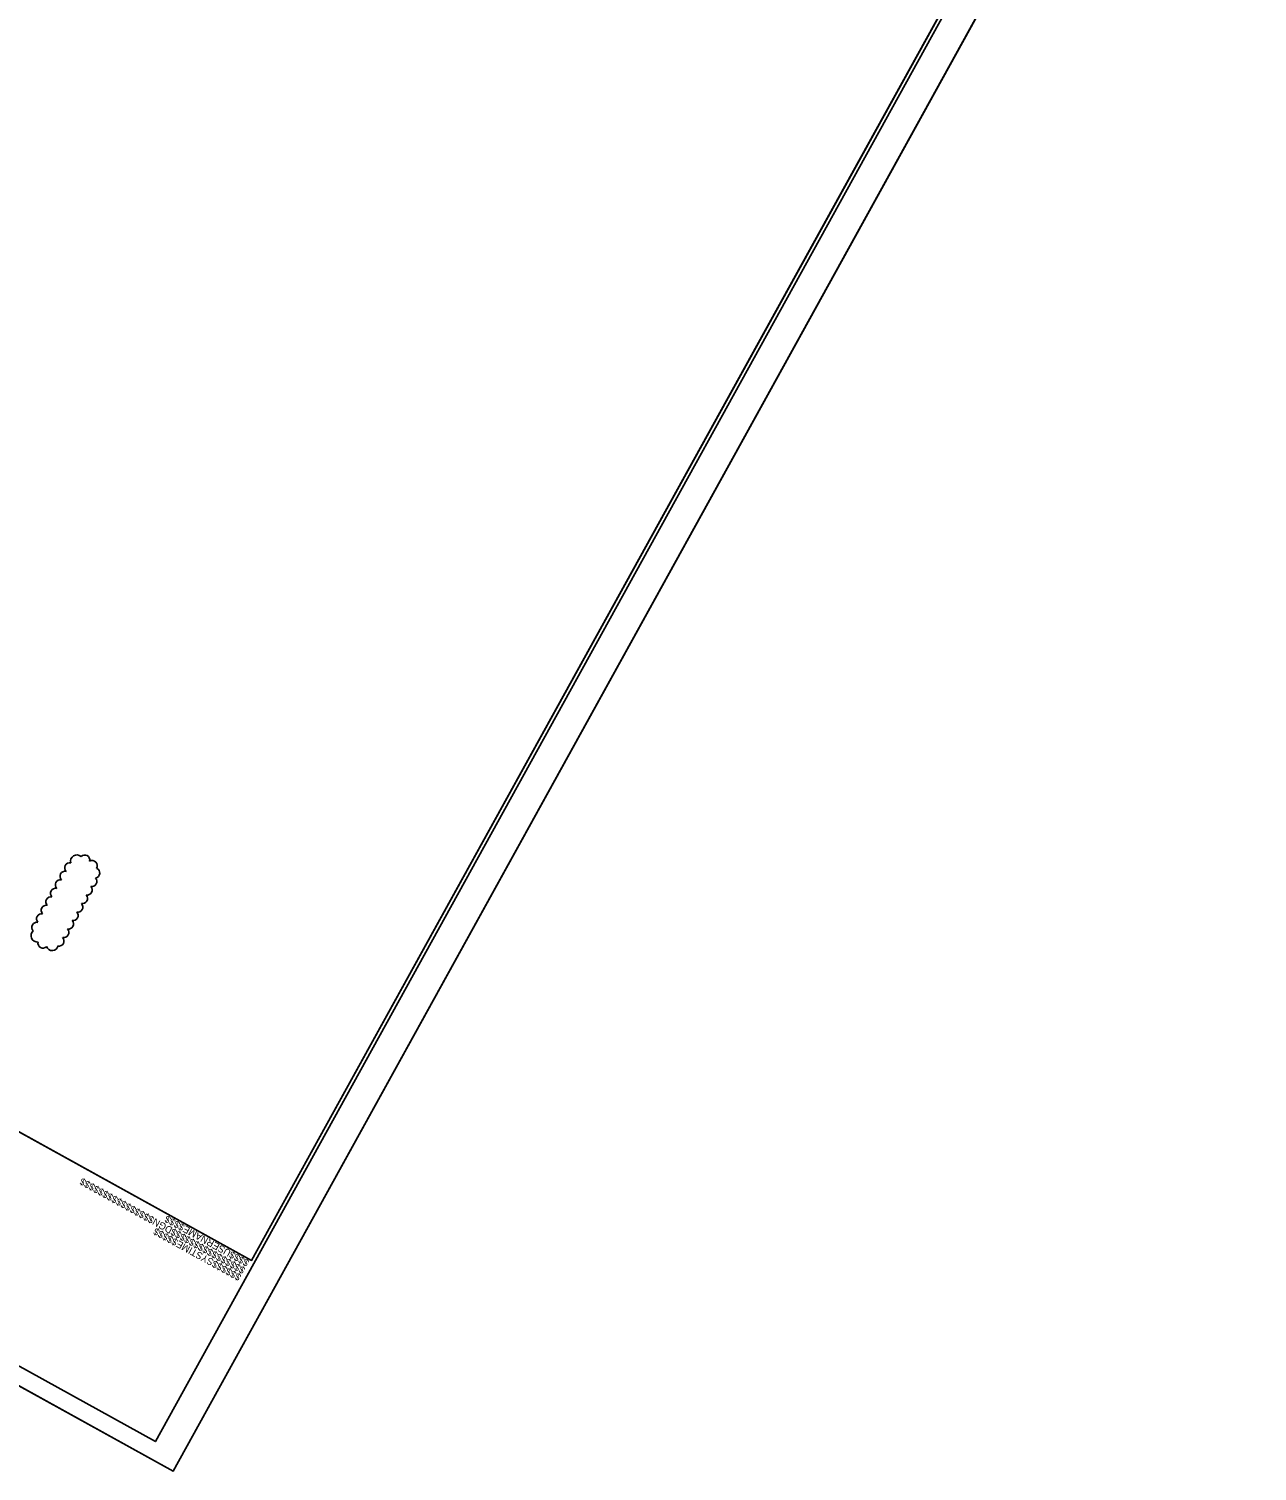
# Model space of a CAD drawing. Extents: x 2176096 to 2177873, y 76962 to 79129.
# Drawn here: x 2176950 to 2177873, y 76962 to 78046 of the extents above; entities that cross this region are included whole.
import ezdxf

# ---------------------------------------------------------------- set-up
doc = ezdxf.new("R2010")
doc.units = 0
for name, color, linetype in [('CTL Primary Horizontal and Vertical CELL', 7, 'Continuous'), ('CTL Primary Horizontal CELL', 7, 'Continuous'), ('CTL Primary Horizontal Cogo Elevation', 7, 'Continuous'), ('CTL Primary Horizontal Cogo Number', 7, 'Continuous'), ('Exist Other Culture Sign Cogo Point CELL', 7, 'Continuous'), ('Exist Structure Minor Pipes RCP 18 Inch', 7, 'Continuous')]:
    doc.layers.add(name, color=color, linetype=linetype)

msp = doc.modelspace()

# ---------------------------------------------------------------- linework, layer by layer
at = {"layer": 'CTL Primary Horizontal and Vertical CELL'}
msp.add_lwpolyline([(2176762, 78648.7), (2176276.9, 77771), (2176400.5, 77667.3), (2176500.7, 77583.3), (2176559.2, 77534.4), (2176927.7, 77225.4), (2177117.2, 77120.7), (2177568.3, 77937), (2177830.4, 78411.2), (2177842.7, 78433.6), (2177075.6, 78857.5), (2176978.9, 78682.4), (2176907.9, 78721.6), (2176842.9, 78604)], close=True, dxfattribs=at)
at = {"layer": 'CTL Primary Horizontal CELL'}
msp.add_lwpolyline([(2176927.6, 78953.6), (2176121.5, 77495), (2177045, 76984.7), (2177851, 78443.3)], close=True, dxfattribs=at)
at = {"layer": 'CTL Primary Horizontal Cogo Elevation'}
for p, q in [((2177058.3, 76962.4), (2177872.8, 78436.3)), ((2176095.6, 77494.5), (2177058.3, 76962.4))]:
    msp.add_line(p, q, dxfattribs=at)
at = {"layer": 'CTL Primary Horizontal Cogo Number'}
msp.add_lwpolyline([(2176910.1, 78968.4), (2176095.6, 77494.5), (2177058.3, 76962.4), (2177872.8, 78436.3)], close=True, dxfattribs=at)
at = {"layer": 'Exist Other Culture Sign Cogo Point CELL'}
msp.add_lwpolyline([(2176923.7, 78941.4), (2176198.2, 77628.6), (2177117.2, 77120.7), (2177842.7, 78433.6)], close=True, dxfattribs=at)
at = {"layer": 'Exist Structure Minor Pipes RCP 18 Inch'}
for centre, radius, start, end in [((2176986, 77420.5), 4.8, 49.5336, 194.5336), ((2176991.8, 77421.4), 3.82, 348.5733, 133.5733), ((2176977.1, 77409.2), 3.82, 78.5733, 223.5733), ((2176980.6, 77415.5), 3.82, 78.5733, 223.5733), ((2176997.3, 77417.1), 3.99, 331.5774, 116.5774), ((2176999.3, 77411.7), 3.82, 280.9672, 65.9672), ((2176973.6, 77402.8), 3.82, 78.5733, 223.5733), ((2176993.7, 77398.9), 3.82, 258.5733, 43.5733), ((2176997.2, 77405.3), 3.82, 258.5733, 43.5733), ((2176966.5, 77390), 3.82, 78.5733, 223.5733), ((2176970, 77396.4), 3.82, 78.5733, 223.5733), ((2176990.2, 77392.5), 3.82, 258.5733, 43.5733), ((2176959.5, 77377.3), 3.82, 78.5733, 223.5733), ((2176963, 77383.7), 3.82, 78.5733, 223.5733), ((2176983.1, 77379.8), 3.82, 258.5733, 43.5733), ((2176986.6, 77386.1), 3.82, 258.5733, 43.5733), ((2176955.9, 77370.9), 3.82, 78.5733, 223.5733), ((2176976.1, 77367), 3.82, 258.5733, 43.5733), ((2176979.6, 77373.4), 3.82, 258.5733, 43.5733), ((2176956.3, 77364.6), 4.79, 130.7956, 275.7956), ((2176960.5, 77359.1), 3.82, 168.5733, 313.5733), ((2176972.5, 77360.6), 3.82, 258.5733, 43.5733), ((2176967.4, 77358), 4.53, 200.968, 345.968)]:
    msp.add_arc(centre, radius, start, end, dxfattribs=at)

# ---------------------------------------------------------------- texts
at = {"layer": 'Exist Other Culture Sign Cogo Point CELL'}
for s, p in [('$$$$$$$$$$$$$$$$DGN$$$$$$$$$$$$$$$$', (2177113, 77114.9)), ('$$$$USERNAME$$$$', (2177116, 77120.4)), ('$$$$$$SYSTIME$$$$$', (2177109.9, 77109.7))]:
    msp.add_text(s, height=5.25, rotation=151.0733, dxfattribs=at).set_placement(p)

doc.saveas('drawing.dxf')
